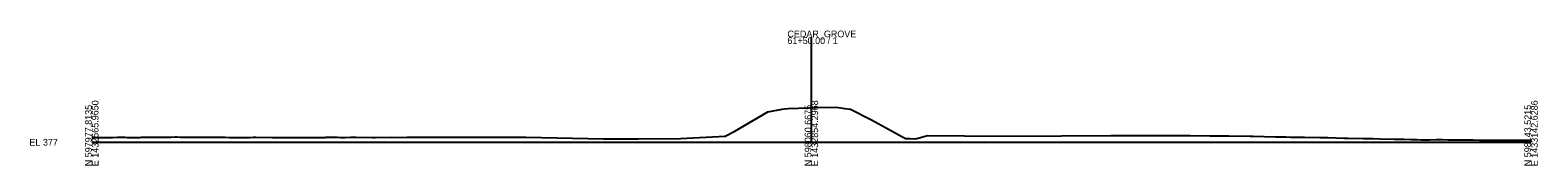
# Model space of a CAD drawing. Extents: x -26 to 2203, y -10 to 12201.
# Drawn here: x -26 to 603, y -10 to 47 of the extents above; entities that cross this region are included whole.
import ezdxf

# ---------------------------------------------------------------- set-up
doc = ezdxf.new("R2010")
doc.units = 0
doc.layers.add('DESIGN - SHEET - Light Grid', color=7, linetype='Continuous')
doc.layers.add('SURVEY - GROUND - Top of Ground', color=7, linetype='Continuous')

msp = doc.modelspace()

# ---------------------------------------------------------------- linework, layer by layer
at = {"layer": 'DESIGN - SHEET - Light Grid'}
for p, q in [((300, 0), (300, 43.76)), ((0, 0), (300, 0)), ((300, 0), (600, 0))]:
    msp.add_line(p, q, dxfattribs=at)
at = {"layer": 'SURVEY - GROUND - Top of Ground'}
for p, q in [((268.14, 4.66), (281.86, 12.75)), ((281.86, 12.75), (287.83, 13.78)), ((287.83, 13.78), (288.78, 13.89)), ((288.78, 13.89), (290.35, 14.12)), ((290.35, 14.12), (298.74, 14.41)), ((298.74, 14.41), (300, 14.46)), ((300, 14.46), (300.33, 14.47)), ((300.33, 14.47), (301.91, 14.48)), ((301.91, 14.48), (310.45, 14.59)), ((310.45, 14.59), (313.98, 14.11)), ((313.98, 14.11), (316.33, 13.77)), ((316.33, 13.77), (325.01, 9.33)), ((325.01, 9.33), (339.17, 1.59)), ((0, 2.04), (0.58, 2.02)), ((0.58, 2.02), (0.96, 2)), ((0.96, 2), (2.6, 2)), ((2.6, 2), (3.56, 2.02)), ((3.56, 2.02), (4.63, 2.03)), ((4.63, 2.03), (6.16, 2.05)), ((6.16, 2.05), (8.33, 2.05)), ((8.33, 2.05), (8.76, 2.05)), ((8.76, 2.05), (10.69, 2.07)), ((10.69, 2.07), (11.37, 2.06)), ((11.37, 2.06), (12.71, 2.09)), ((12.71, 2.09), (13.97, 2.07)), ((13.97, 2.07), (14.73, 2.04)), ((14.73, 2.04), (16.57, 2)), ((16.57, 2), (17.38, 1.99)), ((17.38, 1.99), (18.77, 1.99)), ((18.77, 1.99), (20.17, 2.04)), ((20.17, 2.04), (20.79, 2.06)), ((20.79, 2.06), (22.24, 2.06)), ((22.24, 2.06), (24.37, 2.07)), ((24.37, 2.07), (26.13, 2.06)), ((26.13, 2.06), (28.87, 2.08)), ((28.87, 2.08), (29.57, 2.09)), ((29.57, 2.09), (30.89, 2.14)), ((30.89, 2.14), (32.18, 2.16)), ((32.18, 2.16), (32.91, 2.17)), ((32.91, 2.17), (34.78, 2.21)), ((34.78, 2.21), (35.48, 2.2)), ((35.48, 2.2), (36.96, 2.17)), ((36.96, 2.17), (37.38, 2.17)), ((37.38, 2.17), (44.54, 2.14)), ((44.54, 2.14), (45.44, 2.14)), ((45.44, 2.14), (53.12, 2.1)), ((53.12, 2.1), (54.2, 2.09)), ((54.2, 2.09), (55.59, 2.06)), ((55.59, 2.06), (57.44, 2.02)), ((57.44, 2.02), (59.18, 2)), ((59.18, 2), (59.89, 2.01)), ((59.89, 2.01), (61.2, 2.01)), ((61.2, 2.01), (64.43, 2.03)), ((64.43, 2.03), (65.99, 2.02)), ((65.99, 2.02), (67.28, 2.06)), ((67.28, 2.06), (68.37, 2.08)), ((68.37, 2.08), (75.37, 1.99)), ((75.37, 1.99), (75.94, 1.98)), ((75.94, 1.98), (76.4, 1.98)), ((76.4, 1.98), (76.78, 1.97)), ((76.78, 1.97), (77.1, 1.97)), ((77.1, 1.97), (80.75, 1.98)), ((80.75, 1.98), (85.45, 2.01)), ((85.45, 2.01), (86.8, 2)), ((86.8, 2), (89.25, 2)), ((89.25, 2), (92.01, 2.04)), ((92.01, 2.04), (93.53, 2)), ((93.53, 2), (94.61, 1.99)), ((94.61, 1.99), (95.56, 2)), ((95.56, 2), (97.21, 2.05)), ((97.21, 2.05), (97.58, 2.07)), ((97.58, 2.07), (98.85, 2.11)), ((98.85, 2.11), (99.81, 2.14)), ((99.81, 2.14), (101.62, 2.1)), ((101.62, 2.1), (102.41, 2.08)), ((102.41, 2.08), (103.64, 2.05)), ((103.64, 2.05), (105.01, 2.02)), ((105.01, 2.02), (105.66, 2.03)), ((105.66, 2.03), (107.9, 2.09)), ((107.9, 2.09), (109.7, 2.13)), ((109.7, 2.13), (110.22, 2.13)), ((110.22, 2.13), (116.96, 2.03)), ((116.96, 2.03), (117.53, 2.02)), ((117.53, 2.02), (118.2, 2.02)), ((118.2, 2.02), (124.97, 2.06)), ((124.97, 2.06), (125.87, 2.05)), ((125.87, 2.05), (131.36, 2.07)), ((131.36, 2.07), (133.26, 2.08)), ((133.26, 2.08), (134.04, 2.07)), ((134.04, 2.07), (134.89, 2.09)), ((134.89, 2.09), (139.21, 2.08)), ((139.21, 2.08), (181.15, 2.09)), ((181.15, 2.09), (213.29, 1.48)), ((213.29, 1.48), (227.78, 1.39)), ((227.78, 1.39), (245.37, 1.5)), ((245.37, 1.5), (264.01, 2.51)), ((264.01, 2.51), (268.14, 4.66)), ((339.17, 1.59), (341.02, 1.55)), ((341.02, 1.55), (343.37, 1.41)), ((343.37, 1.41), (345.41, 1.96)), ((345.41, 1.96), (348.44, 2.82)), ((348.44, 2.82), (363.89, 2.71)), ((363.89, 2.71), (375.18, 2.55)), ((375.18, 2.55), (404.22, 2.66)), ((404.22, 2.66), (424.88, 2.87)), ((424.88, 2.87), (457.87, 2.78)), ((457.87, 2.78), (466.15, 2.7)), ((466.15, 2.7), (470.64, 2.65)), ((470.64, 2.65), (474.08, 2.63)), ((474.08, 2.63), (482.87, 2.48)), ((482.87, 2.48), (484.13, 2.49)), ((484.13, 2.49), (493.5, 2.31)), ((493.5, 2.31), (497.81, 2.27)), ((497.81, 2.27), (499.69, 2.19)), ((499.69, 2.19), (500.41, 2.15)), ((500.41, 2.15), (501.71, 2.14)), ((501.71, 2.14), (503.02, 2.14)), ((503.02, 2.14), (503.73, 2.12)), ((503.73, 2.12), (505.62, 2.09)), ((505.62, 2.09), (512.02, 2)), ((512.02, 2), (513.42, 1.97)), ((513.42, 1.97), (513.83, 1.96)), ((513.83, 1.96), (515.27, 1.93)), ((515.27, 1.93), (521.92, 1.76)), ((521.92, 1.76), (523.83, 1.72)), ((523.83, 1.72), (530, 1.62)), ((530, 1.62), (534.23, 1.5)), ((534.23, 1.5), (537.01, 1.48)), ((537.01, 1.48), (543.02, 1.31)), ((543.02, 1.31), (543.91, 1.3)), ((543.91, 1.3), (544.64, 1.27)), ((544.64, 1.27), (545.24, 1.26)), ((545.24, 1.26), (547.14, 1.25)), ((547.14, 1.25), (549.84, 1.18)), ((549.84, 1.18), (550.21, 1.17)), ((550.21, 1.17), (551.48, 1.13)), ((551.48, 1.13), (552.44, 1.12)), ((552.44, 1.12), (554.25, 1.07)), ((554.25, 1.07), (555.04, 1.04)), ((555.04, 1.04), (556.27, 1.04)), ((556.27, 1.04), (557.64, 1.05)), ((557.64, 1.05), (560.53, 1.14)), ((560.53, 1.14), (562.33, 1.13)), ((562.33, 1.13), (563.09, 1.11)), ((563.09, 1.11), (565.45, 1.04)), ((565.45, 1.04), (567.39, 1)), ((567.39, 1), (571.08, 0.99)), ((571.08, 0.99), (575.85, 0.96)), ((575.85, 0.96), (578.5, 0.94)), ((578.5, 0.94), (586.26, 0.92)), ((586.26, 0.92), (586.78, 0.92)), ((586.78, 0.92), (587.69, 0.9)), ((587.69, 0.9), (591.46, 0.87)), ((591.46, 0.87), (592.64, 0.85)), ((592.64, 0.85), (594.06, 0.84)), ((594.06, 0.84), (594.66, 0.85)), ((594.66, 0.85), (596.75, 0.87)), ((596.75, 0.87), (598.7, 0.83)), ((598.7, 0.83), (599.27, 0.82)), ((599.27, 0.82), (600, 0.81))]:
    msp.add_line(p, q, dxfattribs=at)

# ---------------------------------------------------------------- texts
at = {"layer": 'DESIGN - SHEET - Light Grid'}
for s, p in [('CEDAR_GROVE', (290, 43.76)), ('61+50.00 / 1', (290, 40.96)), ('EL 377', (-26, -1.4))]:
    msp.add_text(s, height=2.8, dxfattribs=at).set_placement(p)
for s, p in [('N 597977.8135', (0, -10)), ('E 1432565.9650', (2.8, -10)), ('N 598060.6675', (300, -10)), ('E 1432854.2968', (302.8, -10)), ('N 598143.5215', (600, -10)), ('E 1433142.6286', (602.8, -10))]:
    msp.add_text(s, height=2.8, rotation=90, dxfattribs=at).set_placement(p)

doc.saveas('drawing.dxf')
